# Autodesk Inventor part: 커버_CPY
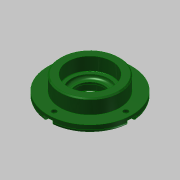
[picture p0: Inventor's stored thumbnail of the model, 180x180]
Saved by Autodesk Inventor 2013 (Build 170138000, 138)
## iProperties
Created: 2016-04
Part Number: 커버_CPY
Material: 강철, 연강
Document SubType Name: Modeling
Designer: Administrator
Mass: 351.567 g
Surface Area: 161.165 cm^2
Volume: 44.7286 cm^3
Density: 7.86 g/cm^3
Company: 한국ATC센터
Author: mdu
Revision Number: 1
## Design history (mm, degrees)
sketch "스케치1"
  geometry: C1 r 38 at (0, 0); 1 further point
  constraints: 1 centre point, 1 coincident
  dimensions: "d0" = 76 diameter of C1
extrude "돌출1" new body sketch "스케치1" distance "d1" = 7; taper "d2" = 0 deg
sketch "스케치2"
  geometry: C1 r 27 at (0, 0); 1 further point
  constraints: 1 centre point, 1 coincident
  dimensions: "d3" = 54 diameter of C1
extrude "돌출2" join sketch "스케치2" distance "d4" = 13; taper "d5" = 0 deg
sketch "스케치3"
  geometry: C1 r 20 at (0, 0); 1 further point
  constraints: 1 centre point, 1 coincident
  dimensions: "d6" = 40 diameter of C1
extrude "돌출3" join sketch "스케치3" distance "d7" = 5; taper "d8" = 0 deg
hole "구멍1" diameter "d11" = 25; stored, may be unused: countersink angle "d15" = 90 deg, drill point angle "d17" = 118 deg; dims "d9" = 10, "d10" = 10, "d12" = 6, "d13" = 32, "d14" = 8.3, "d16" = 8
hole "구멍2" diameter "d20" = 34; stored, may be unused: countersink angle "d24" = 90 deg, drill point angle "d26" = 0 deg; dims "d18" = 10, "d19" = 10, "d21" = 6, "d22" = 40, "d23" = 12, "d25" = 3
fillet "모깎기2" dims "d34" = 3
fillet "모깎기1" dims "d27" = 0.3
chamfer "모따기1" distance "d28" = 1; stored, may be unused: second distance "d29" = 2, angle "d30" = 45 deg
chamfer "모따기2" distance "d31" = 0.8; stored, may be unused: second distance "d32" = 2, angle "d33" = 30 deg
sketch "스케치4" dims "d35" = 65
  geometry: 3 further points
  constraints: 2 horizontal alignment, 1 coincident, 2 other
hole "구멍3" sketch "스케치4" at (32.5, 0) diameter "d36" = 4.5; stored, may be unused: countersink angle "d40" = 90 deg, drill point angle "d42" = 118 deg; dims "d37" = 6, "d38" = 8, "d39" = 4.4, "d41" = 13
sketch "스케치5"
  geometry: L1 (0, 4)-(5.5, 4); L2 (5.5, 4)-(5.5, -4); L3 (5.5, -4)-(0, -4); L4 (0, -4)-(0, 4); C1 r 2.25 at (0, 0) reference; C2 r 38 at (-32.5, 0) reference; 2 further points
  constraints: 8 end point, 3 horizontal, 2 parallel, 1 perpendicular, 1 tangent, 1 vertical alignment, 1 other
extrude "돌출4" cut sketch "스케치5" stored distance "d47" = 24.5; taper "d48" = 0 deg
node "솔리드1"
pattern_circular "원형 패턴1" dims angle "d44" = 360 deg
pattern_circular "원형 패턴2" dims angle "d50" = 360 deg
node "투영된 루프1"
